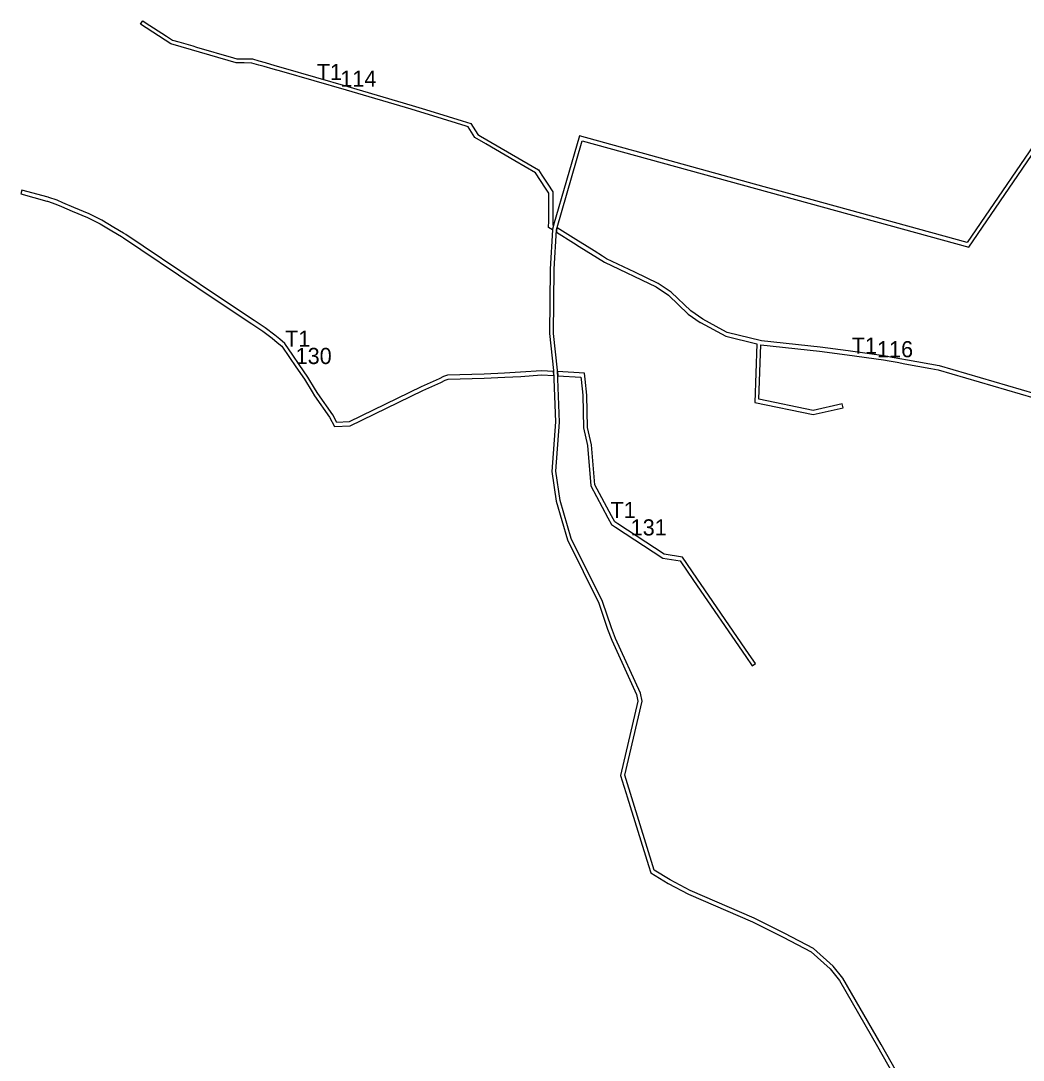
# Model space of a CAD drawing. Extents: x -477001 to -465642, y -1158278 to -1150672.
# Drawn here: x -471989 to -471244, y -1154097 to -1153326 of the extents above; entities that cross this region are included whole.
import ezdxf

# ---------------------------------------------------------------- set-up
doc = ezdxf.new("R2010")
doc.units = 0
for name, color, linetype in [('VPS_id', 7, 'Continuous'), ('VPS_n', 7, 'Continuous'), ('vyvlastneni_n', 7, 'Continuous')]:
    doc.layers.add(name, color=color, linetype=linetype)

msp = doc.modelspace()

# ---------------------------------------------------------------- linework, layer by layer
at = {"layer": 'VPS_n'}
for p, q in [((-471987.87, -1153451.27), (-471988.67, -1153454.16)), ((-471590.89, -1153480.85), (-471591, -1153482.55)), ((-471590.89, -1153480.76), (-471590.89, -1153480.85)), ((-471438.61, -1153563.36), (-471464.14, -1153557.01)), ((-471465.24, -1153559.82), (-471442.11, -1153565.58)), ((-471439.13, -1153566.33), (-471395.52, -1153570.85)), ((-471395.21, -1153567.86), (-471438.61, -1153563.36)), ((-471592.97, -1153588.96), (-471593.08, -1153585.95)), ((-471590.07, -1153586.12), (-471589.96, -1153589.13)), ((-471378.05, -1153613.08), (-471378.68, -1153610.15)), ((-471445.68, -1153804.65), (-471443.2, -1153802.96)), ((-471522.52, -1153952.94), (-471520.82, -1153958.4))]:
    msp.add_line(p, q, dxfattribs=at)
for points in [[(-471880.36, -1153337.1), (-471875.91, -1153339.97), (-471871.38, -1153341.29), (-471871.38, -1153341.29), (-471867.88, -1153342.31), (-471860.97, -1153344.33), (-471858.26, -1153345.11), (-471830.67, -1153353.15), (-471828.23, -1153353.86), (-471817.05, -1153353.97), (-471816.69, -1153353.97), (-471812.01, -1153355.3), (-471807.3, -1153356.64), (-471800.08, -1153358.7), (-471793.96, -1153360.44), (-471745.91, -1153374.31), (-471697.95, -1153388.48), (-471690.57, -1153390.74), (-471681.67, -1153393.47), (-471661.01, -1153399.81), (-471654.58, -1153401.78), (-471649.4, -1153410.03), (-471647.3, -1153411.26), (-471604.23, -1153436.37), (-471601.74, -1153440.2), (-471597.4, -1153446.86), (-471593.63, -1153452.65), (-471593.71, -1153477.11), (-471593.71, -1153477.33), (-471593.13, -1153477.69), (-471593.89, -1153480.32), (-471593.89, -1153480.75), (-471596.72, -1153479), (-471596.71, -1153477.84), (-471596.7, -1153475.32), (-471596.63, -1153453.54), (-471598.94, -1153449.99), (-471606.36, -1153438.6), (-471621.74, -1153429.63), (-471643.47, -1153416.96), (-471651.55, -1153412.25), (-471656.53, -1153404.32), (-471657.9, -1153403.9), (-471682.79, -1153396.27), (-471691.53, -1153393.59), (-471698.81, -1153391.35), (-471746.75, -1153377.19), (-471794.78, -1153363.33), (-471801.19, -1153361.5), (-471808.01, -1153359.56), (-471811.81, -1153358.48), (-471817, -1153357), (-471817.13, -1153356.97), (-471822.84, -1153356.91), (-471828.67, -1153356.86), (-471861.81, -1153347.21), (-471877.14, -1153342.74), (-471877.18, -1153342.73), (-471899.76, -1153328.14), (-471898.34, -1153325.94), (-471898.14, -1153325.62), (-471896.26, -1153326.83), (-471880.4, -1153337.07), (-471880.36, -1153337.1)], [(-471518.29, -1153956.42), (-471540.25, -1153885.85), (-471527.35, -1153830.76), (-471528.58, -1153824.83), (-471547.09, -1153784.31), (-471550.09, -1153776.39), (-471556.65, -1153756.83), (-471579.89, -1153709.91), (-471588.26, -1153681.79), (-471591.27, -1153660.08), (-471588.75, -1153623.57), (-471590.11, -1153585.11), (-471593.12, -1153557.74), (-471592.67, -1153510.14), (-471590.89, -1153480.85), (-471590.89, -1153480.76), (-471571.76, -1153414.78), (-471284.73, -1153493.73), (-471221.49, -1153401.29), (-471197.08, -1153396.57), (-471170.8, -1153425.91), (-471167.61, -1153429.48)], [(-471223.27, -1153398.58), (-471286, -1153490.27), (-471401.07, -1153458.62), (-471436.72, -1153448.81), (-471532.55, -1153422.45), (-471536.3, -1153421.42), (-471573.82, -1153411.1), (-471593.07, -1153477.49), (-471593.13, -1153477.69), (-471593.89, -1153480.32), (-471593.89, -1153480.75), (-471595.67, -1153510.03), (-471596.12, -1153557.89), (-471593.1, -1153585.33), (-471591.75, -1153623.52), (-471594.28, -1153660.18), (-471591.2, -1153682.43), (-471582.69, -1153711.01), (-471559.43, -1153757.98), (-471552.92, -1153777.4), (-471549.86, -1153785.47), (-471531.45, -1153825.77), (-471530.42, -1153830.72), (-471543.35, -1153885.97), (-471540.91, -1153893.83), (-471539.22, -1153899.26), (-471538.44, -1153901.74), (-471522.52, -1153952.94)], [(-471988.67, -1153454.16), (-471969.27, -1153459.5), (-471968.76, -1153459.67), (-471962.75, -1153461.68), (-471958.52, -1153463.47), (-471950.47, -1153466.99), (-471939.11, -1153471.66), (-471929.83, -1153476.31), (-471921.07, -1153481.57), (-471913.99, -1153485.83), (-471912.39, -1153486.79), (-471899.49, -1153495.45), (-471843.57, -1153533.17), (-471817.15, -1153550.65), (-471808.99, -1153556.04), (-471802, -1153561.31), (-471798.33, -1153564.39), (-471794.89, -1153567.2), (-471789.09, -1153575.67), (-471784.37, -1153582.56), (-471778.06, -1153591.77), (-471772.35, -1153601.15), (-471770.5, -1153604.12)], [(-471768, -1153602.46), (-471769.8, -1153599.58), (-471775.54, -1153590.14), (-471781.9, -1153580.86), (-471786.61, -1153573.97), (-471792.66, -1153565.15), (-471796.42, -1153562.08), (-471800.13, -1153558.96), (-471807.26, -1153553.59), (-471815.5, -1153548.15), (-471841.9, -1153530.68), (-471897.82, -1153492.96), (-471910.78, -1153484.26), (-471912.44, -1153483.26), (-471919.52, -1153479), (-471928.38, -1153473.68), (-471937.87, -1153468.93), (-471949.3, -1153464.23), (-471957.33, -1153460.71), (-471961.69, -1153458.87), (-471967.81, -1153456.82), (-471968.4, -1153456.63), (-471987.87, -1153451.27)], [(-471515.43, -1153520.57), (-471532.82, -1153512.29), (-471553.72, -1153502.34), (-471556.64, -1153500.5), (-471562.91, -1153496.55), (-471568.23, -1153493.2), (-471576.62, -1153487.93), (-471590.48, -1153479.34), (-471590.89, -1153480.76)], [(-471591, -1153482.55), (-471578.21, -1153490.47), (-471574.01, -1153493.12), (-471555.17, -1153504.97), (-471516.92, -1153523.18)], [(-471516.92, -1153523.18), (-471507.71, -1153529.43), (-471493.15, -1153543.37), (-471484.13, -1153549.53)], [(-471482.27, -1153547.17), (-471491.25, -1153541.03), (-471505.82, -1153527.09), (-471515.43, -1153520.57)], [(-471484.13, -1153549.53), (-471484.01, -1153549.63), (-471465.24, -1153559.82)], [(-471464.14, -1153557.01), (-471467.3, -1153555.29), (-471482.27, -1153547.17)], [(-471442.11, -1153565.58), (-471443.61, -1153609), (-471400.38, -1153617.93), (-471378.05, -1153613.08)], [(-471378.68, -1153610.15), (-471400.39, -1153614.87), (-471440.53, -1153606.58), (-471439.13, -1153566.33)], [(-471395.52, -1153570.85), (-471375.15, -1153573.66), (-471348.18, -1153577.37), (-471343.75, -1153578.17), (-471337.99, -1153579.22), (-471332.35, -1153580.23), (-471312.85, -1153583.76), (-471307.5, -1153584.72), (-471236.4, -1153605.51), (-471186.96, -1153619.97), (-471180.39, -1153599.2)], [(-471188.94, -1153616.26), (-471235.56, -1153602.63), (-471306.4, -1153581.92), (-471306.81, -1153581.8), (-471330.3, -1153577.56), (-471335.95, -1153576.53), (-471341.63, -1153575.51), (-471347.71, -1153574.41), (-471374.31, -1153570.74), (-471395.17, -1153567.87), (-471395.21, -1153567.86)], [(-471770.5, -1153604.12), (-471759.46, -1153619.84), (-471755.67, -1153626.87), (-471744.19, -1153626.38), (-471690.08, -1153600.15), (-471676.83, -1153594.28), (-471673.47, -1153592.53), (-471671.23, -1153591.67), (-471644.58, -1153591), (-471629.29, -1153590.22), (-471617.44, -1153589.62), (-471601.99, -1153588.47), (-471592.97, -1153588.96)], [(-471593.08, -1153585.95), (-471602.02, -1153585.46), (-471617.63, -1153586.63), (-471629.44, -1153587.22), (-471644.69, -1153588), (-471671.82, -1153588.68), (-471674.7, -1153589.79), (-471678.13, -1153591.58), (-471691.34, -1153597.43), (-471744.94, -1153623.41), (-471753.92, -1153623.79), (-471756.9, -1153618.26), (-471768, -1153602.46)], [(-471443.2, -1153802.96), (-471447.93, -1153796.05), (-471486.59, -1153739.57), (-471497.31, -1153723.94), (-471510.88, -1153721.69), (-471545.36, -1153699.1), (-471547.69, -1153697.57), (-471550.03, -1153693.18), (-471562.33, -1153670.06), (-471564.82, -1153640.44), (-471567.91, -1153627.54), (-471568.41, -1153603.49), (-471569.49, -1153591.61), (-471570.07, -1153587.3), (-471590.07, -1153586.12)], [(-471589.96, -1153589.13), (-471572.71, -1153590.15), (-471572.47, -1153591.95), (-471571.41, -1153603.66), (-471570.9, -1153627.92), (-471567.79, -1153640.92), (-471565.27, -1153670.93), (-471552.68, -1153694.59), (-471549.98, -1153699.66), (-471547.01, -1153701.61), (-471511.99, -1153724.55), (-471499.06, -1153726.69), (-471489.07, -1153741.27), (-471450.41, -1153797.74), (-471445.68, -1153804.65)], [(-471520.82, -1153958.4), (-471507.99, -1153966.13), (-471492.87, -1153974.04), (-471445.33, -1153994.76), (-471422.68, -1154005.98), (-471401.88, -1154017.04), (-471387.73, -1154029.57), (-471380.79, -1154038.15), (-471352.44, -1154087.32), (-471315.4, -1154152.9)], [(-471257.65, -1154328), (-471260.81, -1154267.52), (-471260.89, -1154258.59), (-471262, -1154250.4), (-471270.19, -1154224.63), (-471272.33, -1154220.76), (-471299.24, -1154175.76), (-471312.78, -1154151.43), (-471349.83, -1154085.83), (-471378.31, -1154036.45), (-471385.55, -1154027.49), (-471400.16, -1154014.56), (-471421.31, -1154003.31), (-471444.06, -1153992.04), (-471491.57, -1153971.33), (-471506.52, -1153963.51), (-471518.29, -1153956.42)]]:
    msp.add_lwpolyline(points, dxfattribs=at)
at = {"layer": 'vyvlastneni_n'}
for p, q in [((-471987.87, -1153451.27), (-471988.67, -1153454.16)), ((-471590.89, -1153480.85), (-471591, -1153482.55)), ((-471590.89, -1153480.76), (-471590.89, -1153480.85)), ((-471438.61, -1153563.36), (-471464.14, -1153557.01)), ((-471465.24, -1153559.82), (-471442.11, -1153565.58)), ((-471439.13, -1153566.33), (-471395.52, -1153570.85)), ((-471395.21, -1153567.86), (-471438.61, -1153563.36)), ((-471592.97, -1153588.96), (-471593.08, -1153585.95)), ((-471590.07, -1153586.12), (-471589.96, -1153589.13)), ((-471378.05, -1153613.08), (-471378.68, -1153610.15)), ((-471445.68, -1153804.65), (-471443.2, -1153802.96)), ((-471522.52, -1153952.94), (-471520.82, -1153958.4))]:
    msp.add_line(p, q, dxfattribs=at)
for points in [[(-471880.36, -1153337.1), (-471875.91, -1153339.97), (-471871.38, -1153341.29), (-471871.38, -1153341.29), (-471867.88, -1153342.31), (-471860.97, -1153344.33), (-471858.26, -1153345.11), (-471830.67, -1153353.15), (-471828.23, -1153353.86), (-471817.05, -1153353.97), (-471816.69, -1153353.97), (-471812.01, -1153355.3), (-471807.3, -1153356.64), (-471800.08, -1153358.7), (-471793.96, -1153360.44), (-471745.91, -1153374.31), (-471697.95, -1153388.48), (-471690.57, -1153390.74), (-471681.67, -1153393.47), (-471661.01, -1153399.81), (-471654.58, -1153401.78), (-471649.4, -1153410.03), (-471647.3, -1153411.26), (-471604.23, -1153436.37), (-471601.74, -1153440.2), (-471597.4, -1153446.86), (-471593.63, -1153452.65), (-471593.71, -1153477.11), (-471593.71, -1153477.33), (-471593.13, -1153477.69), (-471593.89, -1153480.32), (-471593.89, -1153480.75), (-471596.72, -1153479), (-471596.71, -1153477.84), (-471596.7, -1153475.32), (-471596.63, -1153453.54), (-471598.94, -1153449.99), (-471606.36, -1153438.6), (-471621.74, -1153429.63), (-471643.47, -1153416.96), (-471651.55, -1153412.25), (-471656.53, -1153404.32), (-471657.9, -1153403.9), (-471682.79, -1153396.27), (-471691.53, -1153393.59), (-471698.81, -1153391.35), (-471746.75, -1153377.19), (-471794.78, -1153363.33), (-471801.19, -1153361.5), (-471808.01, -1153359.56), (-471811.81, -1153358.48), (-471817, -1153357), (-471817.13, -1153356.97), (-471822.84, -1153356.91), (-471828.67, -1153356.86), (-471861.81, -1153347.21), (-471877.14, -1153342.74), (-471877.18, -1153342.73), (-471899.76, -1153328.14), (-471898.34, -1153325.94), (-471898.14, -1153325.62), (-471896.26, -1153326.83), (-471880.4, -1153337.07), (-471880.36, -1153337.1)], [(-471518.29, -1153956.42), (-471540.25, -1153885.85), (-471527.35, -1153830.76), (-471528.58, -1153824.83), (-471547.09, -1153784.31), (-471550.09, -1153776.39), (-471556.65, -1153756.83), (-471579.89, -1153709.91), (-471588.26, -1153681.79), (-471591.27, -1153660.08), (-471588.75, -1153623.57), (-471590.11, -1153585.11), (-471593.12, -1153557.74), (-471592.67, -1153510.14), (-471590.89, -1153480.85), (-471590.89, -1153480.76), (-471571.76, -1153414.78), (-471284.73, -1153493.73), (-471221.49, -1153401.29), (-471197.08, -1153396.57), (-471170.8, -1153425.91), (-471167.61, -1153429.48)], [(-471223.27, -1153398.58), (-471286, -1153490.27), (-471401.07, -1153458.62), (-471436.72, -1153448.81), (-471532.55, -1153422.45), (-471536.3, -1153421.42), (-471573.82, -1153411.1), (-471593.07, -1153477.49), (-471593.13, -1153477.69), (-471593.89, -1153480.32), (-471593.89, -1153480.75), (-471595.67, -1153510.03), (-471596.12, -1153557.89), (-471593.1, -1153585.33), (-471591.75, -1153623.52), (-471594.28, -1153660.18), (-471591.2, -1153682.43), (-471582.69, -1153711.01), (-471559.43, -1153757.98), (-471552.92, -1153777.4), (-471549.86, -1153785.47), (-471531.45, -1153825.77), (-471530.42, -1153830.72), (-471543.35, -1153885.97), (-471540.91, -1153893.83), (-471539.22, -1153899.26), (-471538.44, -1153901.74), (-471522.52, -1153952.94)], [(-471988.67, -1153454.16), (-471969.27, -1153459.5), (-471968.76, -1153459.67), (-471962.75, -1153461.68), (-471958.52, -1153463.47), (-471950.47, -1153466.99), (-471939.11, -1153471.66), (-471929.83, -1153476.31), (-471921.07, -1153481.57), (-471913.99, -1153485.83), (-471912.39, -1153486.79), (-471899.49, -1153495.45), (-471843.57, -1153533.17), (-471817.15, -1153550.65), (-471808.99, -1153556.04), (-471802, -1153561.31), (-471798.33, -1153564.39), (-471794.89, -1153567.2), (-471789.09, -1153575.67), (-471784.37, -1153582.56), (-471778.06, -1153591.77), (-471772.35, -1153601.15), (-471770.5, -1153604.12)], [(-471768, -1153602.46), (-471769.8, -1153599.58), (-471775.54, -1153590.14), (-471781.9, -1153580.86), (-471786.61, -1153573.97), (-471792.66, -1153565.15), (-471796.42, -1153562.08), (-471800.13, -1153558.96), (-471807.26, -1153553.59), (-471815.5, -1153548.15), (-471841.9, -1153530.68), (-471897.82, -1153492.96), (-471910.78, -1153484.26), (-471912.44, -1153483.26), (-471919.52, -1153479), (-471928.38, -1153473.68), (-471937.87, -1153468.93), (-471949.3, -1153464.23), (-471957.33, -1153460.71), (-471961.69, -1153458.87), (-471967.81, -1153456.82), (-471968.4, -1153456.63), (-471987.87, -1153451.27)], [(-471515.43, -1153520.57), (-471532.82, -1153512.29), (-471553.72, -1153502.34), (-471556.64, -1153500.5), (-471562.91, -1153496.55), (-471568.23, -1153493.2), (-471576.62, -1153487.93), (-471590.48, -1153479.34), (-471590.89, -1153480.76)], [(-471591, -1153482.55), (-471578.21, -1153490.47), (-471574.01, -1153493.12), (-471555.17, -1153504.97), (-471516.92, -1153523.18)], [(-471516.92, -1153523.18), (-471507.71, -1153529.43), (-471493.15, -1153543.37), (-471484.13, -1153549.53)], [(-471482.27, -1153547.17), (-471491.25, -1153541.03), (-471505.82, -1153527.09), (-471515.43, -1153520.57)], [(-471484.13, -1153549.53), (-471484.01, -1153549.63), (-471465.24, -1153559.82)], [(-471464.14, -1153557.01), (-471467.3, -1153555.29), (-471482.27, -1153547.17)], [(-471442.11, -1153565.58), (-471443.61, -1153609), (-471400.38, -1153617.93), (-471378.05, -1153613.08)], [(-471378.68, -1153610.15), (-471400.39, -1153614.87), (-471440.53, -1153606.58), (-471439.13, -1153566.33)], [(-471395.52, -1153570.85), (-471375.15, -1153573.66), (-471348.18, -1153577.37), (-471343.75, -1153578.17), (-471337.99, -1153579.22), (-471332.35, -1153580.23), (-471312.85, -1153583.76), (-471307.5, -1153584.72), (-471236.4, -1153605.51), (-471186.96, -1153619.97), (-471180.39, -1153599.2)], [(-471188.94, -1153616.26), (-471235.56, -1153602.63), (-471306.4, -1153581.92), (-471306.81, -1153581.8), (-471330.3, -1153577.56), (-471335.95, -1153576.53), (-471341.63, -1153575.51), (-471347.71, -1153574.41), (-471374.31, -1153570.74), (-471395.17, -1153567.87), (-471395.21, -1153567.86)], [(-471770.5, -1153604.12), (-471759.46, -1153619.84), (-471755.67, -1153626.87), (-471744.19, -1153626.38), (-471690.08, -1153600.15), (-471676.83, -1153594.28), (-471673.47, -1153592.53), (-471671.23, -1153591.67), (-471644.58, -1153591), (-471629.29, -1153590.22), (-471617.44, -1153589.62), (-471601.99, -1153588.47), (-471592.97, -1153588.96)], [(-471593.08, -1153585.95), (-471602.02, -1153585.46), (-471617.63, -1153586.63), (-471629.44, -1153587.22), (-471644.69, -1153588), (-471671.82, -1153588.68), (-471674.7, -1153589.79), (-471678.13, -1153591.58), (-471691.34, -1153597.43), (-471744.94, -1153623.41), (-471753.92, -1153623.79), (-471756.9, -1153618.26), (-471768, -1153602.46)], [(-471443.2, -1153802.96), (-471447.93, -1153796.05), (-471486.59, -1153739.57), (-471497.31, -1153723.94), (-471510.88, -1153721.69), (-471545.36, -1153699.1), (-471547.69, -1153697.57), (-471550.03, -1153693.18), (-471562.33, -1153670.06), (-471564.82, -1153640.44), (-471567.91, -1153627.54), (-471568.41, -1153603.49), (-471569.49, -1153591.61), (-471570.07, -1153587.3), (-471590.07, -1153586.12)], [(-471589.96, -1153589.13), (-471572.71, -1153590.15), (-471572.47, -1153591.95), (-471571.41, -1153603.66), (-471570.9, -1153627.92), (-471567.79, -1153640.92), (-471565.27, -1153670.93), (-471552.68, -1153694.59), (-471549.98, -1153699.66), (-471547.01, -1153701.61), (-471511.99, -1153724.55), (-471499.06, -1153726.69), (-471489.07, -1153741.27), (-471450.41, -1153797.74), (-471445.68, -1153804.65)], [(-471520.82, -1153958.4), (-471507.99, -1153966.13), (-471492.87, -1153974.04), (-471445.33, -1153994.76), (-471422.68, -1154005.98), (-471401.88, -1154017.04), (-471387.73, -1154029.57), (-471380.79, -1154038.15), (-471352.44, -1154087.32), (-471315.4, -1154152.9)], [(-471257.65, -1154328), (-471260.81, -1154267.52), (-471260.89, -1154258.59), (-471262, -1154250.4), (-471270.19, -1154224.63), (-471272.33, -1154220.76), (-471299.24, -1154175.76), (-471312.78, -1154151.43), (-471349.83, -1154085.83), (-471378.31, -1154036.45), (-471385.55, -1154027.49), (-471400.16, -1154014.56), (-471421.31, -1154003.31), (-471444.06, -1153992.04), (-471491.57, -1153971.33), (-471506.52, -1153963.51), (-471518.29, -1153956.42)]]:
    msp.add_lwpolyline(points, dxfattribs=at)

# ---------------------------------------------------------------- texts
at = {"layer": 'VPS_id'}
for s, p in [('114', (-471751.42, -1153374.61)), ('116', (-471352.87, -1153575.47)), ('130', (-471784.59, -1153580.49)), ('131', (-471535.79, -1153707.79))]:
    msp.add_text(s, height=12, dxfattribs=at).set_placement(p)
at = {"layer": 'VPS_n'}
for p in [(-471768.87, -1153369.63), (-471792.47, -1153567.7), (-471371.65, -1153572.81), (-471550.76, -1153694.87)]:
    msp.add_text('T1', height=12, dxfattribs=at).set_placement(p)

doc.saveas('drawing.dxf')
